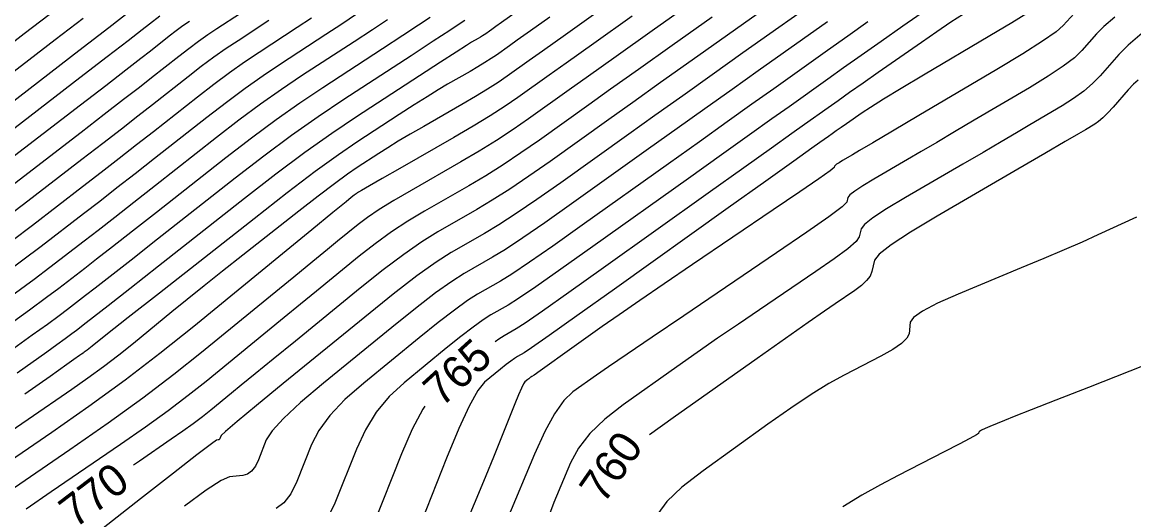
# Model space of a CAD drawing. Extents: x 2079879 to 2092887, y 778083 to 784051.
# Drawn here: x 2084488.3 to 2084585.7, y 781146.9 to 781189.1 of the extents above; entities that cross this region are included whole.
import ezdxf

# ---------------------------------------------------------------- set-up
doc = ezdxf.new("R2010")
doc.units = 0
doc.layers.add('DT_X_Contour_Major', color=7, linetype='Continuous')
doc.layers.add('DT_X_Contour_Minor', color=7, linetype='Continuous')

msp = doc.modelspace()

# ---------------------------------------------------------------- linework, layer by layer
at = {"layer": 'DT_X_Contour_Major'}
for points in [[(2084558.783, 781194.194), (2084550.077, 781188.005), (2084546.979, 781185.803), (2084544.214, 781183.836), (2084541.782, 781182.105), (2084539.683, 781180.61), (2084534.53, 781176.937), (2084532.679, 781175.641), (2084530.991, 781174.505), (2084529.465, 781173.53), (2084528.103, 781172.717), (2084524.686, 781170.762), (2084523.299, 781169.904), (2084521.701, 781168.796), (2084519.893, 781167.437), (2084517.873, 781165.828), (2084512.206, 781161.204), (2084510.262, 781159.617), (2084508.68, 781158.325), (2084507.46, 781157.329), (2084506.601, 781156.627), (2084504.795, 781155.148), (2084504.071, 781154.573), (2084503.253, 781153.957), (2084502.342, 781153.3), (2084501.337, 781152.602), (2084498.534, 781150.687), (2084498.015, 781150.319)], [(2084500.332, 781189.672), (2084499.417, 781188.953), (2084498.778, 781188.456), (2084497.546, 781187.507), (2084495.722, 781186.104), (2084493.307, 781184.248), (2084486.075, 781178.693)], [(2084517.569, 781189.82), (2084516.289, 781188.969), (2084514.868, 781188.038), (2084510.895, 781185.451), (2084509.375, 781184.432), (2084507.797, 781183.317), (2084506.158, 781182.105), (2084504.461, 781180.796), (2084499.856, 781177.177), (2084498.171, 781175.856), (2084496.572, 781174.608), (2084495.057, 781173.433), (2084493.628, 781172.332), (2084489.929, 781169.491), (2084488.322, 781168.278), (2084486.276, 781166.771)], [(2084534.505, 781189.581), (2084532.824, 781188.386), (2084531.645, 781187.547), (2084530.969, 781187.066), (2084529.833, 781186.256), (2084529.369, 781185.938), (2084528.827, 781185.591), (2084528.209, 781185.215), (2084527.513, 781184.809), (2084525.554, 781183.689), (2084524.737, 781183.208), (2084523.757, 781182.606), (2084522.612, 781181.882), (2084521.303, 781181.037), (2084517.594, 781178.621), (2084515.988, 781177.523), (2084513.952, 781176.04), (2084511.486, 781174.172), (2084508.59, 781171.92), (2084500.295, 781165.401), (2084497.565, 781163.255), (2084495.597, 781161.71), (2084494.392, 781160.763), (2084493.949, 781160.416), (2084493.784, 781160.289), (2084493.706, 781160.231), (2084493.598, 781160.151), (2084493.46, 781160.051), (2084493.291, 781159.93), (2084492.798, 781159.579), (2084492.186, 781159.145), (2084490.719, 781158.106), (2084488.511, 781156.543)], [(2084570.766, 781189.832), (2084569.656, 781189.119), (2084568.424, 781188.295), (2084567.07, 781187.361), (2084563.296, 781184.724), (2084561.961, 781183.789), (2084560.784, 781182.963), (2084559.767, 781182.246), (2084558.909, 781181.638), (2084556.832, 781180.162), (2084555.721, 781179.372), (2084553.945, 781178.107), (2084551.503, 781176.367), (2084548.397, 781174.154), (2084539.226, 781167.618), (2084536.168, 781165.445), (2084533.871, 781163.829), (2084532.336, 781162.769), (2084531.561, 781162.266), (2084530.512, 781161.666), (2084530.048, 781161.371), (2084529.719, 781161.136)], [(2084586.078, 781184.059), (2084585.675, 781183.7), (2084585.209, 781183.203), (2084583.883, 781181.695), (2084583.409, 781181.178), (2084582.983, 781180.756), (2084582.604, 781180.431), (2084582.273, 781180.201), (2084581.453, 781179.716), (2084580.852, 781179.363), (2084579.664, 781178.67), (2084577.888, 781177.636), (2084575.526, 781176.262), (2084568.443, 781172.141), (2084566.109, 781170.742), (2084564.416, 781169.634), (2084563.367, 781168.818), (2084562.96, 781168.294), (2084562.731, 781167.285), (2084562.574, 781166.898), (2084562.274, 781166.496), (2084561.833, 781166.077), (2084561.249, 781165.642), (2084559.503, 781164.46), (2084558.585, 781163.829), (2084557.142, 781162.822), (2084555.173, 781161.438), (2084552.679, 781159.679), (2084545.327, 781154.485), (2084543.242, 781152.98)], [(2084523.554, 781155.503), (2084523.368, 781155.235), (2084522.431, 781153.479), (2084521.502, 781151.333), (2084519.033, 781145.088), (2084518.027, 781143.018), (2084516.859, 781141.491), (2084515.531, 781140.507), (2084514.041, 781140.066), (2084509.855, 781139.614), (2084508.314, 781139.336), (2084506.833, 781138.838), (2084505.411, 781138.121), (2084504.049, 781137.185), (2084500.495, 781134.399), (2084498.929, 781133.33), (2084496.899, 781132.215), (2084494.403, 781131.053), (2084491.441, 781129.844), (2084482.924, 781126.557)]]:
    msp.add_lwpolyline(points, dxfattribs=at)
at = {"layer": 'DT_X_Contour_Minor'}
for points in [[(2084570.829, 781192.529), (2084565.461, 781188.777), (2084563.54, 781187.433), (2084561.804, 781186.213), (2084560.252, 781185.119), (2084558.884, 781184.15), (2084555.481, 781181.731), (2084553.973, 781180.658), (2084551.999, 781179.253), (2084549.559, 781177.515), (2084546.654, 781175.445), (2084538.287, 781169.482), (2084535.47, 781167.484), (2084533.295, 781165.964), (2084531.762, 781164.922), (2084530.87, 781164.356), (2084529.347, 781163.485), (2084528.673, 781163.058), (2084527.796, 781162.429), (2084526.716, 781161.599), (2084525.431, 781160.568), (2084521.733, 781157.551), (2084520.432, 781156.338), (2084519.301, 781154.965), (2084518.342, 781153.43), (2084517.554, 781151.734), (2084515.681, 781146.996), (2084514.918, 781145.425)], [(2084558.808, 781191.683), (2084551.428, 781186.437), (2084548.727, 781184.516), (2084546.16, 781182.69), (2084543.726, 781180.957), (2084541.426, 781179.318), (2084535.469, 781175.073), (2084533.377, 781173.602), (2084531.567, 781172.37), (2084530.039, 781171.378), (2084528.794, 781170.627), (2084525.851, 781168.943), (2084524.55, 781168.117), (2084522.855, 781166.902), (2084520.766, 781165.299), (2084518.284, 781163.306), (2084511.137, 781157.475), (2084508.788, 781155.551), (2084507.101, 781154.153), (2084506.076, 781153.282), (2084505.712, 781152.937), (2084505.626, 781152.718), (2084505.591, 781152.646), (2084505.55, 781152.593), (2084505.503, 781152.558), (2084505.451, 781152.543), (2084505.305, 781152.527), (2084504.848, 781152.201), (2084503.585, 781151.234), (2084501.518, 781149.627), (2084498.645, 781147.379), (2084489.913, 781140.531)], [(2084547.375, 781191.143), (2084543.482, 781188.375), (2084540.321, 781186.127), (2084537.893, 781184.4), (2084536.197, 781183.192), (2084532.651, 781180.665), (2084531.283, 781179.719), (2084529.838, 781178.775), (2084528.317, 781177.835), (2084526.719, 781176.897), (2084522.355, 781174.401), (2084520.838, 781173.513), (2084519.56, 781172.719), (2084518.521, 781172.021), (2084517.721, 781171.418), (2084515.905, 781169.936), (2084515.026, 781169.218), (2084513.753, 781168.177), (2084512.084, 781166.811), (2084510.019, 781165.121), (2084503.987, 781160.184), (2084501.569, 781158.264), (2084498.839, 781156.207), (2084495.797, 781154.014), (2084492.443, 781151.684), (2084483.081, 781145.289)], [(2084532.795, 781190.894), (2084530.26, 781189.092), (2084529.768, 781188.743), (2084529.424, 781188.498), (2084529.226, 781188.357), (2084528.894, 781188.12), (2084528.758, 781188.027), (2084528.6, 781187.926), (2084528.419, 781187.816), (2084528.216, 781187.697), (2084527.643, 781187.37), (2084527.197, 781187.094), (2084526.288, 781186.512), (2084524.915, 781185.625), (2084523.079, 781184.432), (2084517.567, 781180.842), (2084515.404, 781179.386), (2084513.049, 781177.709), (2084510.502, 781175.812), (2084507.764, 781173.695), (2084500.207, 781167.756), (2084497.686, 781165.775), (2084495.792, 781164.289), (2084494.525, 781163.297), (2084493.885, 781162.799), (2084493.013, 781162.129), (2084492.605, 781161.823), (2084492.036, 781161.405), (2084491.305, 781160.877), (2084490.412, 781160.238), (2084487.817, 781158.386)], [(2084541.734, 781189.661), (2084538.375, 781187.273), (2084535.949, 781185.547), (2084534.454, 781184.483), (2084531.712, 781182.529), (2084530.59, 781181.761), (2084529.282, 781180.922), (2084527.788, 781180.013), (2084526.107, 781179.033), (2084521.376, 781176.327), (2084519.818, 781175.435), (2084518.695, 781174.792), (2084518.006, 781174.395), (2084517.75, 781174.247), (2084517.647, 781174.18), (2084517.601, 781174.148), (2084517.54, 781174.103), (2084517.463, 781174.045), (2084517.372, 781173.973), (2084517.107, 781173.765), (2084516.656, 781173.399), (2084515.501, 781172.455), (2084513.642, 781170.935), (2084511.078, 781168.837), (2084503.305, 781162.474), (2084500.341, 781160.103), (2084497.277, 781157.764), (2084494.114, 781155.455), (2084490.852, 781153.177), (2084482.02, 781147.143)], [(2084490.628, 781189.769), (2084488.446, 781188.098), (2084482.163, 781183.265)], [(2084493.611, 781189.466), (2084491.153, 781187.578), (2084483.82, 781181.938)], [(2084497.741, 781190.086), (2084495.856, 781188.638), (2084493.242, 781186.631), (2084485.304, 781180.534)], [(2084524.008, 781189.537), (2084523.013, 781188.876), (2084521.629, 781187.966), (2084519.856, 781186.809), (2084514.609, 781183.393), (2084512.602, 781182.048), (2084510.517, 781180.575), (2084508.354, 781178.974), (2084506.113, 781177.246), (2084500.031, 781172.466), (2084497.929, 781170.816), (2084496.182, 781169.449), (2084494.791, 781168.365), (2084493.756, 781167.565), (2084491.471, 781165.81), (2084490.402, 781165.007), (2084488.91, 781163.913), (2084486.995, 781162.528)], [(2084538.751, 781190.07), (2084535.881, 781188.029), (2084533.867, 781186.597), (2084532.711, 781185.774), (2084530.773, 781184.393), (2084529.98, 781183.849), (2084529.055, 781183.257), (2084527.998, 781182.614), (2084526.81, 781181.921), (2084523.465, 781180.008), (2084522.278, 781179.322), (2084521.226, 781178.699), (2084520.309, 781178.139), (2084519.527, 781177.642), (2084517.621, 781176.4), (2084516.765, 781175.812), (2084515.628, 781174.979), (2084514.209, 781173.9), (2084512.509, 781172.575), (2084507.599, 781168.717), (2084505.829, 781167.321), (2084504.205, 781166.029), (2084502.724, 781164.839), (2084501.387, 781163.753), (2084498.016, 781160.993), (2084496.73, 781159.964), (2084495.401, 781158.95), (2084494.029, 781157.948), (2084492.614, 781156.96), (2084488.783, 781154.343), (2084487.214, 781153.263)], [(2084520.291, 781189.348), (2084518.959, 781188.468), (2084517.362, 781187.424), (2084512.752, 781184.422), (2084510.989, 781183.24), (2084509.157, 781181.946), (2084507.256, 781180.539), (2084505.287, 781179.021), (2084499.943, 781174.821), (2084498.05, 781173.336), (2084496.377, 781172.028), (2084494.924, 781170.899), (2084493.692, 781169.948), (2084490.7, 781167.651), (2084489.301, 781166.599), (2084487.348, 781165.167)], [(2084513.618, 781189.47), (2084512.375, 781188.653), (2084509.038, 781186.48), (2084507.762, 781185.625), (2084506.436, 781184.688), (2084505.061, 781183.67), (2084503.635, 781182.571), (2084499.768, 781179.532), (2084498.292, 781178.376), (2084496.767, 781177.188), (2084495.19, 781175.967), (2084493.564, 781174.715), (2084489.158, 781171.332), (2084487.381, 781169.985)], [(2084507.387, 781189.882), (2084505.324, 781188.538), (2084504.535, 781188.01), (2084503.716, 781187.43), (2084502.865, 781186.801), (2084501.984, 781186.121), (2084499.592, 781184.242), (2084498.535, 781183.416), (2084497.156, 781182.347), (2084495.456, 781181.036), (2084493.435, 781179.481), (2084487.617, 781175.012)], [(2084548.726, 781189.574), (2084545.23, 781187.089), (2084542.268, 781184.982), (2084539.837, 781183.252), (2084537.94, 781181.901), (2084533.591, 781178.801), (2084531.981, 781177.68), (2084530.415, 781176.64), (2084528.891, 781175.683), (2084527.411, 781174.807), (2084523.521, 781172.582), (2084522.069, 781171.708), (2084520.631, 781170.757), (2084519.207, 781169.729), (2084517.797, 781168.623), (2084514.056, 781165.57), (2084512.644, 781164.418), (2084511.216, 781163.251), (2084509.772, 781162.07), (2084508.31, 781160.874), (2084504.391, 781157.666), (2084502.82, 781156.418), (2084501.046, 781155.082), (2084499.069, 781153.657), (2084496.89, 781152.143), (2084490.808, 781147.988), (2084488.622, 781146.476)], [(2084576.461, 781189.99), (2084575.014, 781189.088), (2084573.079, 781187.928), (2084567.266, 781184.489), (2084565.295, 781183.317), (2084563.741, 781182.377), (2084562.604, 781181.67), (2084561.884, 781181.196), (2084560.52, 781180.242), (2084560.037, 781179.905), (2084559.612, 781179.606), (2084559.244, 781179.347), (2084558.934, 781179.127), (2084558.183, 781178.594), (2084557.47, 781178.086), (2084555.891, 781176.961), (2084553.448, 781175.22), (2084550.14, 781172.862), (2084540.166, 781165.754), (2084536.866, 781163.406), (2084534.447, 781161.694), (2084532.91, 781160.617), (2084532.253, 781160.176), (2084531.677, 781159.846), (2084531.422, 781159.685), (2084531.091, 781159.447), (2084530.682, 781159.133), (2084530.196, 781158.743), (2084528.797, 781157.601), (2084528.194, 781156.863), (2084527.435, 781155.506), (2084526.52, 781153.529), (2084525.449, 781150.932), (2084522.385, 781143.181)], [(2084580.457, 781189.904), (2084579.51, 781188.828), (2084578.88, 781188.285), (2084577.697, 781187.465), (2084575.962, 781186.366), (2084573.675, 781184.989), (2084566.84, 781180.946), (2084564.556, 781179.595), (2084562.828, 781178.574), (2084561.657, 781177.884), (2084561.043, 781177.523), (2084560.148, 781177.003), (2084559.853, 781176.826), (2084559.639, 781176.686), (2084559.506, 781176.583), (2084559.455, 781176.516), (2084559.426, 781176.389), (2084559.085, 781176.123), (2084558.083, 781175.419), (2084556.42, 781174.279), (2084554.097, 781172.702), (2084547.02, 781167.914), (2084544.535, 781166.227), (2084542.388, 781164.757), (2084540.578, 781163.503), (2084539.105, 781162.465), (2084535.629, 781159.988), (2084534.484, 781159.172), (2084533.654, 781158.583), (2084533.142, 781158.221), (2084532.945, 781158.086), (2084532.842, 781158.027), (2084532.797, 781157.998), (2084532.738, 781157.956), (2084532.665, 781157.9), (2084532.578, 781157.83), (2084532.329, 781157.627), (2084532.203, 781157.45), (2084532.014, 781157.072), (2084531.762, 781156.493), (2084531.446, 781155.714), (2084530.518, 781153.368), (2084530.106, 781152.34), (2084529.566, 781151.018), (2084528.897, 781149.401), (2084528.1, 781147.489), (2084525.803, 781141.997)], [(2084584.02, 781189.582), (2084583.065, 781188.75), (2084582.424, 781188.106), (2084581.132, 781186.637), (2084580.482, 781186.021), (2084579.5, 781185.275), (2084578.186, 781184.399), (2084576.541, 781183.393), (2084571.711, 781180.536), (2084569.988, 781179.518), (2084568.44, 781178.606), (2084567.068, 781177.801), (2084565.871, 781177.103), (2084562.913, 781175.382), (2084561.938, 781174.798), (2084561.232, 781174.335), (2084560.793, 781173.995), (2084560.623, 781173.776), (2084560.528, 781173.354), (2084560.116, 781172.958), (2084558.951, 781172.087), (2084557.035, 781170.74), (2084554.366, 781168.918), (2084546.246, 781163.424), (2084543.485, 781161.553), (2084541.291, 781160.06), (2084539.664, 781158.945), (2084538.605, 781158.208), (2084536.537, 781156.747), (2084535.744, 781155.996), (2084534.919, 781154.838), (2084534.06, 781153.275), (2084533.168, 781151.305), (2084530.745, 781145.511)], [(2084509.881, 781189.267), (2084507.181, 781187.509), (2084506.149, 781186.817), (2084505.076, 781186.059), (2084503.963, 781185.236), (2084502.809, 781184.346), (2084499.68, 781181.887), (2084498.414, 781180.896), (2084496.961, 781179.767), (2084495.323, 781178.501), (2084493.499, 781177.098), (2084488.388, 781173.172), (2084486.44, 781171.691)], [(2084502.922, 781189.202), (2084502.355, 781188.802), (2084501.767, 781188.366), (2084501.158, 781187.897), (2084499.505, 781186.597), (2084498.656, 781185.936), (2084497.351, 781184.927), (2084495.589, 781183.57), (2084493.371, 781181.864), (2084486.846, 781176.853)], [(2084527.067, 781189.282), (2084526.658, 781189.009), (2084525.735, 781188.403), (2084524.299, 781187.465), (2084522.349, 781186.195), (2084516.466, 781182.363), (2084514.216, 781180.855), (2084511.878, 781179.203), (2084509.452, 781177.409), (2084506.938, 781175.47), (2084500.119, 781170.111), (2084497.807, 781168.296), (2084495.987, 781166.869), (2084494.658, 781165.831), (2084493.821, 781165.182), (2084492.242, 781163.97), (2084491.504, 781163.415), (2084490.473, 781162.659), (2084489.15, 781161.703), (2084487.534, 781160.546)], [(2084558.833, 781189.172), (2084552.779, 781184.868), (2084550.476, 781183.23), (2084548.106, 781181.544), (2084545.67, 781179.81), (2084543.169, 781178.027), (2084536.409, 781173.21), (2084534.075, 781171.563), (2084532.143, 781170.235), (2084530.613, 781169.226), (2084529.486, 781168.537), (2084527.016, 781167.124), (2084525.925, 781166.431), (2084524.502, 781165.411), (2084522.75, 781164.066), (2084520.666, 781162.394), (2084514.669, 781157.5), (2084512.669, 781155.813), (2084511.168, 781154.424), (2084510.165, 781153.331), (2084509.66, 781152.536), (2084508.978, 781150.811), (2084508.7, 781150.239), (2084508.377, 781149.817), (2084508.01, 781149.545), (2084507.599, 781149.424), (2084506.442, 781149.299), (2084505.714, 781148.984), (2084504.397, 781148.135), (2084502.491, 781146.75)], [(2084562.39, 781189.161), (2084560.628, 781187.916), (2084558.858, 781186.661), (2084554.13, 781183.3), (2084552.224, 781181.944), (2084550.052, 781180.398), (2084547.615, 781178.662), (2084544.911, 781176.736), (2084537.348, 781171.346), (2084534.772, 781169.523), (2084532.719, 781168.099), (2084531.187, 781167.074), (2084530.178, 781166.446), (2084528.181, 781165.304), (2084527.299, 781164.744), (2084526.149, 781163.92), (2084524.733, 781162.832), (2084523.048, 781161.481), (2084518.201, 781157.525), (2084516.55, 781156.076), (2084515.235, 781154.694), (2084514.254, 781153.381), (2084513.607, 781152.135), (2084512.33, 781148.903), (2084511.809, 781147.832), (2084511.205, 781147.042), (2084510.517, 781146.533)], [(2084586.414, 781188.178), (2084585.204, 781187.124), (2084584.391, 781186.307), (2084582.754, 781184.446), (2084582.084, 781183.757), (2084581.303, 781183.086), (2084580.41, 781182.432), (2084579.407, 781181.797), (2084576.582, 781180.126), (2084575.42, 781179.441), (2084574.052, 781178.638), (2084572.478, 781177.719), (2084570.698, 781176.682), (2084565.678, 781173.762), (2084564.023, 781172.77), (2084562.824, 781171.985), (2084562.08, 781171.407), (2084561.791, 781171.035), (2084561.629, 781170.32), (2084561.345, 781169.928), (2084560.613, 781169.291), (2084559.434, 781168.408), (2084557.808, 781167.28), (2084552.874, 781163.942), (2084551.035, 781162.691), (2084549.216, 781161.441), (2084547.419, 781160.192), (2084545.642, 781158.943), (2084540.932, 781155.616), (2084539.318, 781154.362), (2084538.01, 781153.094), (2084537.008, 781151.814), (2084536.312, 781150.52), (2084534.862, 781147.053), (2084534.391, 781145.815)], [(2084585.919, 781172.048), (2084582.524, 781170.492), (2084581.15, 781169.873), (2084579.577, 781169.186), (2084577.803, 781168.43), (2084575.828, 781167.604), (2084570.296, 781165.31), (2084568.477, 781164.51), (2084567.168, 781163.833), (2084566.368, 781163.277), (2084566.079, 781162.842), (2084565.989, 781161.846), (2084565.808, 781161.442), (2084565.335, 781160.977), (2084564.569, 781160.451), (2084563.51, 781159.863), (2084560.295, 781158.215), (2084558.973, 781157.483), (2084557.421, 781156.523), (2084555.637, 781155.334), (2084553.621, 781153.917), (2084547.938, 781149.834), (2084546.078, 781148.396), (2084544.761, 781147.143), (2084543.986, 781146.075)], [(2084590.21, 781160.479), (2084581.714, 781157.147), (2084578.866, 781156.029), (2084576.693, 781155.173), (2084575.195, 781154.579), (2084574.372, 781154.246), (2084573.079, 781153.71), (2084572.654, 781153.529), (2084572.349, 781153.388), (2084572.165, 781153.287), (2084572.101, 781153.226), (2084572.091, 781153.117), (2084571.899, 781152.984), (2084571.33, 781152.668), (2084570.385, 781152.169), (2084569.062, 781151.486), (2084565.034, 781149.421), (2084563.487, 781148.601), (2084561.867, 781147.689), (2084560.176, 781146.685)]]:
    msp.add_lwpolyline(points, dxfattribs=at)

# ---------------------------------------------------------------- texts
at = {"layer": 'DT_X_Contour_Major'}
for s, rotation, p in [('765', 42.41118, (2084525.022, 781155.344)), ('760', 55.16936, (2084539.224, 781146.844)), ('770', 37.17238, (2084492.888, 781144.729))]:
    msp.add_text(s, height=2.8, rotation=rotation, dxfattribs=at).set_placement(p)

doc.saveas('drawing.dxf')
